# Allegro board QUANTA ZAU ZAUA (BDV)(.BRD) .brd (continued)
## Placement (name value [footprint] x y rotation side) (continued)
C20002  N16@4.7u/6.3V_4  [C0402_2]  105.67 107.97 0 top
C20003  N16@0.1u/16V_4  [C0402]  105.98 110.73 0 top
C20004  N16@1u/6.3V_4  [C0402]  104.2 109.84 0 top
C20005  EV@0.1u/16V_4  [C0402]  102.65 122.85 0 bottom
C20006  N16@0.1u/16V_4  [C0402]  119.53 124.33 270 top
C20016  N16@0.22u/10V_4  [C0402]  90.49 99.81 180 bottom
C20017  N16@1000p/50V_4  [C0402]  88.45 101.51 90 bottom
C20020  N16@1000p/50V_4  [C0402]  85.28 92.72 270 bottom
C20021  *N16@1000p/25V_2  [C0201]  84.96 94.8 270 top
C20022  47U/6.3V_6  [C0603]  108.01 50.28 90 top
C20023  *47U/6.3V_6  [C0603]  103.69 46.47 90 top
C20024  *180p/50V_4  [C0402]  150.94 22.9 90 top
C20025  180p/50V_4  [C0402]  56.45 103.52 90 bottom
C20026  180p/50V_4  [C0402]  60.13 102.22 270 bottom
CN1  50281-00201-001  [50281-00201-001-2P-L]  14.3 3.45 180 bottom
CN2  USB-097-1R09HG  [UB3-USB-097-1R09HG-9P]  7.4 54.44 90 bottom
CN3  USB-097-1R09HG  [UB3-USB-097-1R09HG-9P]  7.4 34.44 90 bottom
CN8  2RJ1622-001111F  [RJ45-2RJ1622-001111F-8P]  10.05 96.2 90 bottom
CN10  TPC@USB3.1  [UB31-C12321-1242D-L-24P]  1.46 15.9 90 bottom
CN13  KBL@50505-00401-V01  [50505-00401-V01-4P-L]  204.32 10.95 180 bottom
CN14  PBA@196241-08021-3  [196241-08021-3-8P-L]  58.7 18.15 180 bottom
CN15  ODD@132F18-100000-A2-R  [132F18-100000-A2-R-18P-L]  132.6 14.35 180 bottom
CN16  SSD@NASM0-S6701-TSH4  [NGFF-NASM0-S6701-TSH4-KM-SMT]  30.6 4.35 180 bottom
CN17  NASE0-S6701-TS40  [NGFF-NASE0-S6701-TS40-KE-SMT]  188.5 21.88 270 bottom
CN18  FOR15_17@196153-28021-35  [50584-0280N-V02-28P-L]  161.5 18.5 180 bottom
CN19  FOR14@196153-28021-35  [50584-0280N-V02-28P-L]  139.9 23.2 180 bottom
CN24  *51578-00401-V01  [FPC-51578-00401-V01-4P-L]  45.7 8.75 180 bottom
CN29  196538-40041-3  [196538-40041-3-40P-L]  53.6 110.3 0 bottom
CN33  51653-0080N-V02  [196047-08021-3-8P-L]  72.82 18.55 180 bottom
CN35  51619-04001-V04  [51619-04001-V04-40P-L]  216.25 38.15 270 bottom
CN36  51325-00401-001  [51325-00401-001-4P-L]  117.8 17.6 180 bottom
CN37  10444-19001  [HDMI-10591-19001-19P]  3.4 76.2 90 bottom
CN38  *50208-00401-V02  [50208-00401-V02-4P-L]  35.1 118.05 0 bottom
D3  1N4148WS  [D-SOD323-1_85X1_25-0_95H]  55.69 111.49 0 top
D4  EV@RB500V-40  [D-SOD323-1_85X1_25-0_95H]  90.1 99.3 270 top
D11  1N4148WS  [D-SOD323-1_85X1_25-0_95H]  192.26 33.01 270 bottom
D12  *RB500V-40  [D-SOD323-1_85X1_25-0_95H]  210.98 23.2 0 top
D13  RB500V-40  [D-SOD323-1_85X1_25-0_95H]  204.2 22.29 270 top
D14  BAT54AW-L  [SOT23-1_7-65-3P]  25.64 69.33 180 top
D16  TPC@EGA10402V05AH_0.2p  [R0402]  12.03 19.26 90 top
D17  TPC@EGA10402V05AH_0.2p  [R0402]  12.08 13.45 270 top
D18  TPC@EGA10402V05AH_0.2p  [R0402]  10.63 19.47 0 top
D19  TPC@EGA10402V05AH_0.2p  [R0402]  14.26 13.22 90 top
D20  GS@RB500V-40  [D-SOD323-1_85X1_25-0_95H]  51.14 15.3 0 top
D21  GS@RB500V-40  [D-SOD323-1_85X1_25-0_95H]  50.68 17.16 0 top
D22  *TPM@PESD5V0F1BL  [R0402]  130.08 21.35 0 top
D33  AZ5725-01F.R7G  [ESD-1X0_6-2P]  151.7 20.36 0 top
D50  *AZ5725-01F.R7G  [ESD-1X0_6-2P]  14.92 83.86 180 top
D51  *RB500V-40  [D-SOD323-1_85X1_25-0_95H]  167.45 30.49 0 top
D60  *RB500V-40  [D-SOD323-1_85X1_25-0_95H]  170.01 31 270 top
D61  RB500V-40  [D-SOD323-1_85X1_25-0_95H]  167.19 28.97 0 top
D62  *RB500V-40  [D-SOD323-1_85X1_25-0_95H]  167.19 27.44 0 top
D63  RB500V-40  [D-SOD323-1_85X1_25-0_95H]  177.23 23.48 270 top
D64  *RB500V-40  [D-SOD323-1_85X1_25-0_95H]  167.45 32.02 0 top
D65  TVM0G5R5M220R_22p  [R0402]  182.31 29.96 270 top
D2012  BAT54CW  [SOT23-1_7-65-3P]  50 26.55 180 top
D2016  *RB500V-40  [D-SOD323-1_85X1_25-0_95H]  167.19 25.92 0 top
D6541  TPC@P4SMAFJ20A  [D-3_8X2_5]  15.56 13.52 270 bottom
D6542  TPC@PDZ5.6B  [D-SOD323-1_7X1_25-PMEG4005AEA]  15.66 9.08 270 top
D6543  1N4148WS  [D-SOD323-1_85X1_25-0_95H]  193.79 33.26 270 bottom
D13081  *PESD5V0H1BSF  [D-0_6X0_3-0_32H-SMT]  13.9 79.87 0 top
D13082  *PESD5V0H1BSF  [D-0_6X0_3-0_32H-SMT]  13.9 78.85 0 top
D13083  *PESD5V0H1BSF  [D-0_6X0_3-0_32H-SMT]  13.78 77.96 270 bottom
D13084  *PESD5V0H1BSF  [D-0_6X0_3-0_32H-SMT]  13.78 76.57 90 bottom
D13085  *PESD5V0H1BSF  [D-0_6X0_3-0_32H-SMT]  13.78 75.93 270 top
D13086  *PESD5V0H1BSF  [D-0_6X0_3-0_32H-SMT]  13.78 74.54 90 top
D13087  *PESD5V0H1BSF  [D-0_6X0_3-0_32H-SMT]  13.78 82.03 270 bottom
D13088  *PESD5V0H1BSF  [D-0_6X0_3-0_32H-SMT]  13.78 80.63 90 bottom
D13089  *PESD5V0H1BSF  [D-0_6X0_3-0_32H-SMT]  13.78 74.79 270 bottom
D13090  *PESD5V0H1BSF  [D-0_6X0_3-0_32H-SMT]  13.78 73.39 90 bottom
EC7  *PBA@AZ5725-01F.R7G  [ESD-1X0_6-2P]  57.39 22.52 0 bottom
EC8  *PBA@AZ5725-01F.R7G  [ESD-1X0_6-2P]  59.22 22.52 0 bottom
EC9  SSD@10u/6.3V_4  [C0402_2]  25 4.76 0 top
EC10  SSD@10u/6.3V_4  [C0402_2]  26.53 6.87 90 top
EC11  SSD@0.1u/16V_2  [C0201]  27.01 8.88 0 top
EC12  *33p/50V_4  [C0402]  196.2 19.19 0 bottom
EC13  *220p/50V_4  [C0402]  167.42 16.98 270 top
EC6500  TPC@22u/6.3V_6  [C0603]  13.7 22.19 0 bottom
FAN3  50278-00401-001  [WTB-50278-00401-V01-4P-L]  171.72 29.5 90 bottom
HD1  HDD@51625-01201-001  [51625-01201-001-12P-L]  217.53 13.57 270 bottom
HE1  APX8132AI-TRG  [SOT23-2_38-95-3P]  34.9 122.75 90 top
HOLE1  *HG-O335X315D252X232P2  [HG-O335X315D252X232P2]  11.25 109.2 180 bottom
HOLE2  *HG-C354I158D118P2  [HG-C354I158D118P2]  17.48 68.15 0 top
HOLE3  *HG-ZAU-2  [HG-ZAU-2]  5.2 4.4 0 top
HOLE4  *HG-C354I274D220P2  [HG-C354I274D220P2]  86.2 15.5 180 bottom
HOLE5  EV@H-C256I186D102P2  [H-C256I186D102P2]  90.53 123.23 180 bottom
HOLE6  EV@H-C256I186D102P2  [H-C256I186D102P2]  119.53 84.23 180 bottom
HOLE7  *H-TIC157BC276D150P2  [H-TIC157BC276D150P2]  71.88 89.73 180 bottom
HOLE8  *H-TIC157BC276D150P2  [H-TIC157BC276D150P2]  71.88 27.73 180 bottom
HOLE9  *H-TIC157BC276D150P2  [H-TIC157BC276D150P2]  106.88 58.74 180 bottom
HOLE10  *H-S158D158N  [H-S158D158N]  110.17 72.38 0 top
HOLE11  *hg-zau-1  [HG-ZAU-1]  136.2 123.5 0 top
HOLE12  *H-C98D98N  [H-C98D98N]  142.5 123.5 180 bottom
HOLE13  *HG-C276D126P2  [HG-C276D126P2]  216.55 54 0 top
HOLE14  -  [H-DAVIDOFF-1]  216.8 21.88 180 bottom
HOLE15  *SPAD-DAVIDOFF-1  [SPAD-DAVIDOFF-1]  43.94 123.9 0 top
HOLE16  *SPAD-C354NP  [SPAD-C354NP]  41.2 10 0 top
HOLE17  *SPAD-C315NP  [SPAD-C315NP]  131.79 64.66 0 top
HOLE18  *SPAD-C354NP  [SPAD-C354NP]  140.49 22.1 0 top
HOLE19  *SPAD-RE209X315NP  [SPAD-RE209X315NP]  215.74 37.1 0 top
HOLE20  *SPAD-RE197X138NP  [SPAD-RE197X138NP]  3.35 108.2 90 bottom
HOLE21  *h-c79d79n  [H-C75D75N]  4.2 24 0 top
HOLE22  *2D-BARCODE-6X6-S  [2D-BARCODE-6X6-S]  18.02 104.15 0 bottom
J2000  *JUMP  [JOPEN25X30_S]  52.89 25.13 0 top
JDIM2000  D4AS0-26001-1P40  [DDR4-D4AS0-26001-1P40-STD-SMT]  54.35 62.83 270 bottom
L4  N17@HCB1005KF-330T30  [R0402]  113.22 84.82 90 bottom
L5  EV@HCB1608KF_300_2A  [R0603]  120.08 115.3 90 top
L7  N17@HCB1005KF-330T30  [R0402]  89.85 103.64 180 top
L8  N17@HCB1005KF-330T30  [R0402]  87.95 107.05 180 top
L11  BLM15AG121SN1D  [R0402]  202.07 19.19 180 top
L12  BLM15AG601SN1D  [R0402]  52.49 110.76 0 top
L13  BLM15AG601SN1D  [R0402]  51.14 111.14 270 top
L15  PBY160808T-600Y-N  [R0603]  210.37 29.45 0 top
L16  HCB2012KF-220T60  [R0805]  202.42 31.8 0 top
L23  HCB1005KF-330T30  [R0402]  75.3 18.05 270 top
L24  HCB1005KF-330T30  [R0402]  74.33 18.05 270 top
L28  HCB1608KF-121T30  [R0603]  210.63 33.64 0 bottom
L29  BLM15AG121SN1D  [R0402]  202.25 16.35 270 top
L30  BLM15AG121SN1D  [R0402]  183.93 31.86 270 top
L31  N16@HCB1005KF-330T30  [R0402]  89.92 104.63 180 top
L32  N16@HCB1005KF-330T30  [R0402]  88.33 105.52 270 top
NOREF  -  [unnamed]  127.85 122.72 0 top
NOREF#2  -  [#2]  62.93 70.47 0 top
NOREF#3  -  [#2]  82.61 -18.56 0 top
NOREF#4  -  [#2]  31.81 -59.2 0 top
NOREF#5  -  [unnamed]  23.56 116.19 0 top
NOREF#6  -  [unnamed]  208.51 43.28 0 top
NOREF#7  -  [#2]  26 23.86 180 bottom
NOREF#8  -  [unnamed]  129.6 121.78 180 bottom
NOREF#9  -  [unnamed]  208.6 43.42 180 bottom
NOREF#10  -  [unnamed]  25.29 115.81 180 bottom
PC1  1000p/50V_4  [C0402]  44 121.59 90 top
PC2  0.047u/50V_6  [C0603]  45.91 121.96 0 top
PC3  0.1u/25V_4  [C0402]  130.24 26.78 0 bottom
PC4  0.1u/25V_4  [C0402]  124.71 25.78 0 bottom
PC5  0.1u/50V_4  [C0402]  42 121.68 180 bottom
PC6  0.1u/25V_4  [C0402]  131.58 27.34 90 bottom
PC7  2200p/50V_4  [C0402]  134.04 40.84 270 top
PC8  0.01u/50V_4  [C0402]  133 27.29 90 top
PC9  2.2u/10V_4  [C0402]  132.15 29.22 90 top
PC10  *47p/50V_4  [C0402]  105.4 15.35 0 top
PC11  *47p/50V_4  [C0402]  103.95 15.1 270 top
PC12  0.1u/50V_4  [C0402]  135.23 40.39 270 top
PC13  2200p/50V_4  [C0402]  12 118.5 270 top
PC14  0.1u/50V_4  [C0402]  39.13 121.5 0 bottom
PC15  0.047u/50V_6  [C0603]  129.7 29.63 0 top
PC16  0.47u/25V_6  [C0603]  129.73 31.23 0 bottom
PC17  *0.01u/50V_4  [C0402]  123.62 28.59 90 top
PC18  *100p/50V_4  [C0402]  136.72 30.93 270 top
PC19  *680p/50V_6  [C0603]  128.28 28.21 180 top
PC20  100p/50V_4  [C0402]  136.72 32.65 270 top
PC25  0.1u/50V_4  [C0402]  132.9 33.9 90 bottom
PC35  0.1u/50V_4  [C0402]  133.13 32.53 90 top
PC36  0.1u/50V_4  [C0402]  134.09 32.53 270 top
PC37  100p/50V_4  [C0402]  138.14 33.67 0 bottom
PC51  2200p/50V_4  [C0402]  53.2 20.28 270 bottom
PC81  *0.1u/25V_4  [C0402]  113.42 34.37 270 bottom
PC82  *680p/50V_6  [C0603]  116.62 37.25 0 top
PC83  22u/6.3V_6  [C0603]  120.2 62.34 180 top
PC152  *2200p/50V_4  [C0402]  124.85 57.57 270 top
PC162  *330u/2V_7343H1.9  [CC7343]  62.6 88.1 90 bottom
PC164  22u/25V_8  [C0805]  111.32 34.33 180 bottom
PC165  2200p/50V_4  [C0402]  104.92 25.5 270 bottom
PC166  22u/25V_8  [C0805]  112.12 31.73 270 bottom
PC167  0.1u/50V_4  [C0402]  107.07 25.62 90 bottom
PC168  *100p/50V_4  [C0402]  105.88 25.5 270 bottom
PC170  10u/25V_8  [C0805]  114.89 34.07 270 bottom
PC172  2200p/50V_4  [C0402]  127.55 31.46 180 bottom
PC217  10u/25V_6  [C0603]  117.49 34.1 0 bottom
PC218  2200p/50V_4  [C0402]  127.78 43.8 90 bottom
PC219  *22U/6.3V_6  [C0603]  112.69 39.94 180 top
PC220  22u/6.3V_6  [C0603]  112.69 34.23 180 top
PC221  *0.01u/50V_4  [C0402]  125.63 35.57 270 bottom
PC222  22u/6.3V_6  [C0603]  116.14 35.19 270 top
PC224  22u/6.3V_6  [C0603]  112.69 37.1 180 top
PC225  *1000p/50V_4  [C0402]  122.29 36.77 0 bottom
PC227  22u/6.3V_6  [C0603]  114.72 34.25 270 top
PC228  *0.047u/6.3V_2  [C0201]  121.35 41.26 0 bottom
PC229  10u/6.3V_6  [C0603]  166.56 24.24 0 top
PC230  22u/6.3V_6  [C0603]  112.69 38.52 180 top
PC231  *22U/6.3V_6  [C0603]  112.69 35.65 180 top
PC232  0.047u/6.3V_2  [C0201]  119.04 41.39 90 bottom
PC233  0.1u/16V_4  [C0402]  117.36 35.55 270 top
PC234  10u/6.3V_6  [C0603]  117.28 41.74 0 bottom
PC235  0.1u/25V_4  [C0402]  114.9 40.17 180 top
PC236  *22U/6.3V_6  [C0603]  107.83 43.6 0 top
PC242  4.7u/6.3V_4  [C0402_2]  159.02 23.79 270 bottom
PC267  *150p/50V_4  [C0402]  69.4 122.01 270 top
PC268  1u/6.3V_2  [C0201]  61.1 125.46 0 top
PC276  *0.1u/16V_4  [C0402]  63.89 124.55 270 top
PC280  0.1u/16V_4  [C0402]  67.98 124.93 180 bottom
PC283  *0.1u/16V_4  [C0402]  65.26 124.17 180 top
PC285  *1u/6.3V_4  [C0402]  67.75 117.74 0 top
PC288  10u/25V_6  [C0603]  56.86 119.32 180 bottom
PC289  10u/25V_6  [C0603]  62.08 120.33 0 bottom
PC290  0.1u/25V_4  [C0402]  57.01 121.75 0 bottom
PC292  2200p/50V_4  [C0402]  57.01 120.79 0 bottom
PC293  *0.1u/16V_4  [C0402]  51.45 123.89 270 top
PC294  22u/6.3V_6  [C0603]  51.98 123.66 270 bottom
PC295  22u/6.3V_6  [C0603]  49.06 121.86 0 top
PC296  22u/6.3V_6  [C0603]  54.21 123.64 270 bottom
PC297  22u/6.3V_6  [C0603]  49.03 121.55 0 bottom
PC298  0.033u/10V_4  [C0402]  68.36 123.58 270 bottom
PC299  10u/6.3V_6  [C0603]  68.16 119.54 90 top
PC300  *2200p/50V_4  [C0402]  59.5 117.03 180 top
PC301  0.1u/25V_4  [C0402]  64.88 116.32 0 top
PC302  10u/6.3V_6  [C0603]  64.81 124.57 180 bottom
PC304  10u/6.3V_6  [C0603]  69.15 124.62 270 top
PC305  *22u/6.3V_8  [C0805]  56.37 123.86 270 bottom
PC306  *22u/6.3V_8  [C0805]  48.95 119.29 0 bottom
PC423  *0.1u/6.3V_2  [C0201]  138.01 59.68 90 bottom
PC551  *2200p/50V_6  [C0603]  36.76 31.74 180 top
PC561  0.1u/6.3V_2  [C0201]  37.02 27.7 270 top
PC562  22u/6.3V_6  [C0603]  35.34 27.42 0 top
PC563  22u/6.3V_6  [C0603]  33.84 29.58 270 top
PC571  10u/6.3V_4  [C0402_2]  45.02 30.19 270 top
PC572  0.01u/50V_4  [C0402]  43.93 30.19 270 top
PC574  *22p/50V_4  [C0402]  41.01 27.47 270 top
PC581  *0.1u/6.3V_2  [C0201]  39.41 27.55 270 top
PC756  0.1u/16V_4  [C0402]  139.95 30.17 180 bottom
PC6000  0.1u/25V_4  [C0402]  138.14 34.63 180 bottom
PC6001  0.1u/25V_4  [C0402]  148.1 35.14 90 bottom
PC6002  2200p/50V_4  [C0402]  142.49 30.75 270 bottom
PC6003  0.1u/25V_4  [C0402]  141.53 30.75 270 bottom
PC6004  22u/25V_8  [C0805]  141.12 32.6 0 bottom
PC6005  *10u/25V_6  [C0603]  141.1 34.57 0 bottom
PC6006  *680p/50V_6  [C0603]  142.3 28.71 0 bottom
PC6007  0.1u/16V_4  [C0402]  144.52 31.41 270 top
PC6008  22u/6.3V_6  [C0603]  156.48 35.77 270 bottom
PC6009  22u/6.3V_6  [C0603]  150.13 35.19 0 top
PC6010  22u/6.3V_6  [C0603]  156.96 35.47 270 top
PC6011  *22U/6.3V_6  [C0603]  155.48 35.34 270 top
PC6012  *22U/6.3V_6  [C0603]  159.07 35.65 180 top
PC6013  0.1u/16V_4  [C0402]  159.47 35.5 180 bottom
PC6014  22u/6.3V_6  [C0603]  157.89 35.77 270 bottom
PC6015  1u/25V_4  [C0402]  157.41 27.6 180 top
PC6016  1u/25V_4  [C0402]  152.61 27.93 90 top
PC6017  0.1u/16V_4  [C0402]  144.37 33.12 180 top
PC6018  10u/6.3V_6  [C0603]  158.05 23.48 90 top
PC6019  0.1u/16V_4  [C0402]  156.86 23.58 90 top
PC6020  0.1u/16V_4  [C0402]  153.96 23.63 90 top
PC6021  10u/6.3V_6  [C0603]  152.74 23.56 90 top
PC6022  1u/10V_4  [C0402]  143.95 34.38 0 bottom
PC6023  4.7u/6.3V_4  [C0402_2]  144.04 35.73 270 bottom
PC6024  10P/50V_4  [C0402]  144.31 35.34 0 top
PC6025  0.1u/16V_4  [C0402]  154.14 27.72 0 bottom
PC6026  *0.1u/16V_4  [C0402]  156.55 29.07 90 bottom
PC6027  *0.1u/16V_4  [C0402]  152.41 27.72 180 bottom
PC6028  1000p/50V_4  [C0402]  155.89 23.58 90 top
PC6029  1000p/50V_4  [C0402]  154.93 23.58 90 top
PC6030  0.1u/25V_4  [C0402]  50.55 18.63 270 bottom
PC6031  0.1u/25V_4  [C0402]  48.79 18.79 90 bottom
PC6032  22u/25V_8  [C0805]  51.27 15.64 90 bottom
PC6033  *10u/25V_6  [C0603]  47.31 18.84 270 bottom
PC6034  2200p/50V_4  [C0402]  51.51 18.63 90 bottom
PC6035  0.1u/25V_4  [C0402]  40.56 16.37 0 top
PC6036  1u/25V_4  [C0402]  24.01 23.02 180 top
PC6037  1u/25V_4  [C0402]  23.05 30.01 270 top
PC6038  *680p/50V_6  [C0603]  43.62 18.4 270 top
PC6039  0.1u/16V_4  [C0402]  49.31 14.51 270 bottom
PC6040  10u/6.3V_6  [C0603]  21.75 23.15 270 top
PC6041  0.1u/16V_4  [C0402]  21.3 24.98 180 top
PC6042  0.1u/16V_4  [C0402]  21.7 29.63 180 top
PC6043  10u/6.3V_6  [C0603]  18.73 29.58 0 top
PC6044  22u/6.3V_6  [C0603]  31.74 19.53 270 bottom
PC6045  22u/6.3V_6  [C0603]  37.03 15.92 180 top
PC6046  22u/6.3V_6  [C0603]  34.6 13.17 0 bottom
PC6047  22u/6.3V_6  [C0603]  37.03 18.19 180 top
PC6048  *22U/6.3V_6  [C0603]  36.76 19.93 180 top
PC6049  *22U/6.3V_6  [C0603]  34.76 15.02 90 top
PC6050  0.1u/16V_4  [C0402]  32.73 14.08 90 bottom
PC6051  0.1u/16V_4  [C0402]  24.95 27.34 180 top
PC6052  *0.1u/16V_4  [C0402]  24.95 26.38 180 top
PC6053  *0.1u/16V_4  [C0402]  24.95 28.31 180 top
PC6054  4.7u/10V_4  [C0402]  42.42 14.17 90 bottom
PC6055  0.1u/16V_4  [C0402]  44.59 15.23 270 bottom
PC6056  1000p/50V_4  [C0402]  18.78 26.88 0 top
PC6057  1000p/50V_4  [C0402]  18.78 27.9 0 top
PC6058  1u/10V_4  [C0402]  43.62 15.23 90 bottom
PC6059  10P/50V_4  [C0402]  45.93 13.77 180 bottom
PC6228  0.1u/16V_4  [C0402]  77.89 25.67 90 bottom
PC6229  0.47u/6.3V_4  [C0402]  162.49 26.28 270 top
PC6230  10u/6.3V_6  [C0603]  171.89 22.47 180 bottom
PC6231  0.1u/16V_4  [C0402]  170.06 22.59 270 bottom
PC7000  0.22u/25V_4  [C0402]  135.32 50.02 90 top
PC7001  1000p/50V_4  [C0402]  140.27 58.15 90 top
PC7003  *0.1u/6.3V_2  [C0201]  141.79 56.76 0 top
PC7004  0.47u/6.3V_2  [C0201]  140.65 53.83 180 top
PC7005  *0.1u/6.3V_2  [C0201]  143.22 60.64 0 bottom
PC7006  *0.1u/6.3V_2  [C0201]  141.79 53.83 180 top
PC7007  *100p/50V_4  [C0402]  145.58 50.38 180 top
PC7008  *100p/50V_4  [C0402]  143.6 51.29 0 top
PC7009  *100p/50V_4  [C0402]  145.58 49.41 180 top
PC7010  330p/16V_2  [C0201]  143.95 46.72 90 bottom
PC7011  82p/50V_4  [C0402]  142.45 48.17 180 bottom
PC7012  *68p/50V_4  [C0402]  143.01 45.1 90 bottom
PC7013  *100p/50V_4  [C0402]  138.36 57.52 90 top
PC7014  *100p/50V_4  [C0402]  133.41 60.03 0 bottom
PC7015  *100p/50V_4  [C0402]  135.7 56.88 180 top
PC7016  270p/50V_4  [C0402]  133.4 56.11 0 bottom
PC7017  82p/50V_4  [C0402]  133.4 58.06 180 bottom
PC7018  *68p/50V_4  [C0402]  133.4 54.17 0 bottom
PC7019  *100p/50V_4  [C0402]  144.12 51.31 0 bottom
PC7020  560p/50V_4  [C0402]  145.89 51.26 180 bottom
PC7021  68p/50V_4  [C0402]  144.77 54.88 270 bottom
PC7022  *100p/50V_4  [C0402]  143.5 53.28 180 top
PC7023  *68p/50V_4  [C0402]  145.25 53.1 180 top
PC7024  *100p/50V_4  [C0402]  144.2 53.51 180 bottom
PC7025  0.1u/6.3V_2  [C0201]  137.86 48.37 270 bottom
PC7026  4.7u/6.3V_4  [C0402]  135.7 51.8 180 top
PC7027  0.1u/6.3V_2  [C0201]  139.76 45.06 90 bottom
PC7029  0.1u/6.3V_2  [C0201]  143.65 56.53 270 bottom
PC7030  0.1u/6.3V_2  [C0201]  136.21 59.68 270 bottom
PC7031  22u/25V_8  [C0805]  131 69.07 90 bottom
PC7032  *10u/25V_6  [C0603]  128.54 73.67 270 bottom
PC7033  10u/25V_6  [C0603]  130.52 73.67 270 bottom
PC7034  0.1u/25V_4  [C0402]  131.08 70.17 90 top
PC7035  2200p/50V_4  [C0402]  132.04 70.17 270 top
PC7036  *15u/25V_3528H1.9  [C3528]  129.52 33.64 180 bottom
PC7037  *10u/25V_8  [C0805]  123.35 69.3 90 bottom
PC7038  0.1u/25V_4  [C0402]  133.03 70.17 90 top
PC7039  *0.1u/16V_4  [C0402]  116.27 60.18 180 top
PC7040  22u/6.3V_6  [C0603]  109.79 67.68 270 bottom
PC7041  22u/6.3V_6  [C0603]  111.82 67.68 270 bottom
PC7042  *22u/6.3V_8  [C0805]  115 64.63 180 bottom
PC7043  *22u/6.3V_8  [C0805]  113.85 67.68 270 bottom
PC7044  *330u/2V_7343H1.9  [CC7343]  119.16 51.17 270 bottom
PC7045  330u/2V_7343H1.9  [CC7343]  119.19 61.76 90 bottom
PC7046  *2200p/50V_4  [C0402]  130.85 65.34 180 bottom
PC7047  0.47u/6.3V_4  [C0402]  138.75 48.5 90 bottom
PC7049  U42P@22u/25V_8  [C0805]  123.12 47.81 270 bottom
PC7050  *U42P@10u/25V_6  [C0603]  122.49 45.2 0 bottom
PC7051  U42P@10u/25V_6  [C0603]  130.87 48.58 270 bottom
PC7052  *U42P@10u/25V_6  [C0603]  130.87 44.36 90 bottom
PC7053  U42P@0.1u/25V_4  [C0402]  126.81 43.8 90 bottom
PC7054  U42P@2200p/50V_4  [C0402]  125.79 43.8 270 bottom
PC7055  U42P@0.1u/25V_4  [C0402]  124.78 43.8 90 bottom
PC7056  U42P@0.22u/25V_4  [C0402]  133.31 44.82 0 bottom
PC7057  U42P@0.1u/16V_4  [C0402]  122.92 49.97 0 bottom
PC7058  U42P@22u/6.3V_6  [C0603]  109.08 47.99 90 bottom
PC7059  U42P@22u/6.3V_6  [C0603]  100.98 51.83 90 bottom
PC7060  U42P@22u/6.3V_6  [C0603]  111.06 47.99 90 bottom
PC7061  U42P@22u/6.3V_6  [C0603]  107.07 49.52 90 bottom
PC7062  U42P@330u/2V_7343H1.9  [CC7343]  114.41 51.17 270 bottom
PC7063  U42P@1u/6.3V_4  [C0402]  134.86 50.46 180 bottom
PC7064  *U42P@2200p/50V_4  [C0402]  131.38 51.7 270 bottom
PC7065  U42P@0.47u/6.3V_4  [C0402]  139.76 48.5 90 bottom
PC7066  22u/25V_8  [C0805]  139.3 37.17 270 bottom
PC7067  *10u/25V_6  [C0603]  141.41 37.2 270 bottom
PC7068  0.1u/25V_4  [C0402]  141.57 38.06 180 top
PC7069  2200p/50V_4  [C0402]  141.9 36.14 0 top
PC7070  0.1u/25V_4  [C0402]  141.9 37.1 180 top
PC7072  22u/6.3V_6  [C0603]  114.97 44.64 270 bottom
PC7073  22u/6.3V_6  [C0603]  112.94 44.69 270 bottom
PC7074  *22u/6.3V_8  [C0805]  124.47 41.9 180 bottom
PC7075  *22u/6.3V_8  [C0805]  119.8 44.74 270 bottom
PC7076  *22u/6.3V_8  [C0805]  124.14 37.07 90 bottom
PC7077  *22u/6.3V_8  [C0805]  116.95 44.74 270 bottom
PC7078  *2200p/50V_4  [C0402]  137.83 40.69 90 top
PC7079  0.47u/6.3V_4  [C0402]  143.95 56.73 180 top
PC7080  10u/25V_6  [C0603]  124 78.85 315 bottom
PC7081  *10u/25V_6  [C0603]  116.64 72.79 315 bottom
PC7082  *10u/25V_6  [C0603]  121.32 70.27 90 bottom
PC7083  22u/25V_8  [C0805]  119.14 73.16 315 bottom
PC7084  0.1u/25V_4  [C0402]  124.04 78.19 315 top
PC7085  2200p/50V_4  [C0402]  124.75 78.95 135 top
PC7086  0.1u/25V_4  [C0402]  123.28 79.44 225 top
PC7087  *0.1u/16V_4  [C0402]  93.15 79.92 315 top
PC7088  22u/6.3V_6  [C0603]  77.66 83.37 180 bottom
PC7089  22u/6.3V_6  [C0603]  72.32 84.77 270 bottom
PC7090  *22u/6.3V_8  [C0805]  77.66 81.19 180 bottom
PC7091  *22u/6.3V_8  [C0805]  83.79 84.04 90 bottom
PC7092  *22u/6.3V_8  [C0805]  81.62 85.96 90 bottom
PC7093  *22u/6.3V_8  [C0805]  70.34 84.77 270 bottom
PC7094  330u/2V_7343H1.9  [CC7343]  104.71 78.09 270 bottom
PC7095  *330u/2V_7343H1.9  [CC7343]  107.69 85.2 0 bottom
PC7096  *2200p/50V_4  [C0402]  120.16 78.28 45 top
PC7097  0.47u/6.3V_4  [C0402]  133.49 58.28 0 top
PC7099  0.1u/25V_4  [C0402]  143.32 57.69 180 top
PC7100  *1000p/25V_4  [C0402]  133.49 57.26 0 top
PC7101  0.22u/25V_4  [C0402]  127.9 76.43 0 top
PC7102  1u/6.3V_4  [C0402]  129.7 78.55 90 bottom
PC7103  0.22u/25V_4  [C0402]  140.63 40.2 0 top
PC7104  1u/6.3V_4  [C0402]  142.8 41.1 0 bottom
PC7105  0.22u/25V_4  [C0402]  118.78 70.29 180 top
PC7106  1u/6.3V_4  [C0402]  116.98 68.11 270 bottom
PC9000  EV@2.2u/10V_4  [C0402]  79.11 110.84 180 top
PC9001  *EV@10u/25V_6  [C0603]  73.12 121.79 180 top
PC9002  EV@10u/25V_6  [C0603]  72.62 124.73 180 top
PC9003  EV@0.1u/25V_4  [C0402]  62.19 118.81 0 bottom
PC9004  EV@1u/25V_6  [C0603]  69.02 112.1 0 top
PC9005  EV@10u/25V_6  [C0603]  72.67 123.28 180 top
PC9006  EV@2200p/50V_4  [C0402]  62.15 121.81 0 bottom
PC9007  *EV@15u/25V_3528H1.9  [C3528]  71.57 123.56 180 bottom
PC9008  EV@0.22u/25V_4  [C0402]  76.69 114.41 0 top
PC9009  EV@22u/6.3V_6  [C0603]  108.69 122.23 0 bottom
PC9010  EV@330u/2V_7343H1.9  [CC7343]  80.63 121.47 180 top
PC9011  EV@330u/2V_7343H1.9  [CC7343]  115 123.61 0 bottom
PC9012  *EV@2200p/50V_4  [C0402]  74.99 118.17 0 top
PC9013  N17@0.22u/10V_4  [C0402]  72.5 115.76 0 top
PC9014  *EV@0.22u/10V_4  [C0402]  71.94 106.67 270 top
PC9015  *EV@10u/25V_6  [C0603]  81.47 101.46 90 bottom
PC9016  *EV@10u/25V_6  [C0603]  79.46 101.46 90 bottom
PC9017  EV@22u/25V_8  [C0805]  83.45 101.46 90 bottom
PC9018  EV@0.1u/25V_4  [C0402]  78.5 106.01 270 bottom
PC9019  EV@2200p/50V_4  [C0402]  77.51 106.01 270 bottom
PC9020  EV@0.22u/25V_4  [C0402]  77.81 108.34 45 top
PC9021  EV@330u/2V_7343H1.9  [CC7343]  110.25 123.43 180 top
PC9022  EV@22u/6.3V_6  [C0603]  108.62 124.95 0 bottom
PC9023  EV@0.1u/16V_4  [C0402]  69.56 113.32 0 top
PC9024  *EV@2200p/50V_4  [C0402]  83.07 106.59 0 top
PC9025  SP@4700p/25V_4  [C0402]  74.1 112.91 90 bottom
PC9026  EV@1500p/50V_4  [C0402]  70.67 114.29 180 top
PC9027  EV@56p/50V_4  [C0402]  69.48 108.75 0 bottom
PC9028  *EV@100p/50V_4  [C0402]  69.89 110.3 270 bottom
PC9029  EV@56p/50V_4  [C0402]  69.51 111.64 0 bottom
PC9030  *EV@56p/50V_4  [C0402]  73.7 108.62 270 bottom
PC9053  EV@1u/25V_4  [C0402]  20.9 90.28 90 top
PC9054  EV@1u/25V_4  [C0402]  25.11 90.28 90 top
PC9055  EV@10u/6.3V_4  [C0402]  20.76 98.41 0 top
PC9056  EV@0.1u/16V_4  [C0402]  20.76 97.14 0 top
PC9057  EV@0.1u/16V_4  [C0402]  25.46 95.24 180 top
PC9058  EV@10u/6.3V_4  [C0402]  25.46 96.51 180 top
PC9059  EV@0.1u/16V_4  [C0402]  22.9 90.28 90 top
PC9060  *EV@0.1u/16V_4  [C0402]  23.91 90.28 90 top
PC9062  EV@1000p/50V_4  [C0402]  22.41 96.63 270 top
PC9063  EV@1000p/50V_4  [C0402]  23.43 96.63 270 top
PC9064  *EV@820p/50V_4  [C0402]  21.88 90.28 90 top
PC9065  EV@0.1u/16V_4  [C0402]  63.51 95.77 0 bottom
PC9066  EV@10u/6.3V_6  [C0603]  63.38 94.5 0 bottom
PC9067  EV@10u/6.3V_6  [C0603]  70.04 95.74 180 bottom
PC9068  EV@10u/6.3V_6  [C0603]  70.04 97.27 180 bottom
PC9069  EV@0.1u/16V_4  [C0402]  70.17 94.47 180 bottom
PC9071  EV@0.01u/50V_4  [C0402]  76.77 93.08 90 bottom
PC9072  EV@0.1u/16V_4  [C0402]  77 99.96 180 bottom
PC9073  EV@0.22u/10V_4  [C0402]  77.79 93.84 90 bottom
PC9074  *EV@0.01u/50V_4  [C0402]  139.13 62.09 180 bottom
PC9075  EV@10u/6.3V_6  [C0603]  141.59 72.09 180 bottom
PC9076  *EV@0.1u/25V_4  [C0402]  137.02 62.83 0 top
PC9077  EV@2200p/50V_4  [C0402]  135.75 61.25 0 bottom
PC9078  EV@10u/25V_8  [C0805]  136.46 62.75 0 bottom
PC9079  EV@0.1u/25V_4  [C0402]  137.96 70.34 180 bottom
PC9080  EV@22u/6.3V_6  [C0603]  142.1 74.38 90 bottom
PC9081  EV@22u/6.3V_6  [C0603]  139.23 74.36 90 bottom
PC9082  EV@22u/6.3V_6  [C0603]  142.25 74.38 90 top
PC9083  EV@22u/6.3V_6  [C0603]  140.8 74.38 90 top
PC9084  EV@22u/6.3V_6  [C0603]  139.38 74.36 90 top
PC9085  *EV@22U/6.3V_6  [C0603]  137.96 74.36 90 top
PC9086  *EV@22U/6.3V_6  [C0603]  140.65 74.38 90 bottom
PC9087  EV@0.1u/16V_4  [C0402]  136.74 74.66 90 top
PC9088  *EV@680p/50V_6  [C0603]  136.64 67.91 270 top
PC9089  *EV@1000p/50V_4  [C0402]  141.46 64.78 180 bottom
PC9090  EV@1u/6.3V_2  [C0201]  141.69 67.83 0 bottom
PC9091  EV@0.01u/50V_4  [C0402]  140.53 69.47 180 bottom
PC9097  *22p/50V_4  [C0402]  161.1 26.91 180 top
PC9098  *22U/6.3V_6  [C0603]  35.37 29.58 270 top
PD2  P4SMAFJ20A  [D-3_8X2_5]  16.5 115.18 180 top
PD3  PDZ5.6B  [D-SOD323-1_7X1_25-PMEG4005AEA]  107.91 16.85 90 top
PD4  PDZ5.6B  [D-SOD323-1_7X1_25-PMEG4005AEA]  109.41 16.62 90 top
PD9001  EV@1SS355  [D-SOD323-1_85X1_25-0_95H]  75.12 96.51 90 bottom
PD9002  BAT54CW  [SOT23-1_7-65-3P]  132.4 35.29 0 top
PJ1  50458-00801-V02  [WTB-50458-00801-V02-8P-L]  102.45 16.42 180 bottom
PJ2  SP@30706-00042-001  [DCJK-30706-00042-001-3P-SMT]  1.85 116.6 90 bottom
PJ3005  0.001_1%_3720  [RC3720-SMT]  107.71 35.83 0 top
PJ3008  0.001_1%_3720  [RC3720-SMT]  165.8 21.58 0 top
PJ6001  0.001_1%_3720  [RC3720-SMT]  154.85 32.12 180 top
PJ6003  0.001_1%_3720  [RC3720-SMT]  33.59 18.53 90 top
PJ7001  *short3720  [SHORT3720]  51.27 116.32 180 bottom
PJ9002  EV@0.001_1%_3720  [RC3720-SMT]  140.65 78.6 180 bottom
PJ9003  *EV@short_8  [S0805]  70.17 99.05 180 bottom
PJ9005  0.001_1%_3720  [RC3720-SMT]  30.95 29.96 180 top
PL5  6.8uH/4.5A_7x7x3  [L6_6X6_6-2_8H]  118.93 28.9 180 bottom
PL12  1uH/11A_7x7x3  [L6_6X6_6-2_8H]  109.92 38.72 180 bottom
PL14  2.2uH/1.67A_2.5x2.0x1.2  [L2_5X2-1_2H]  166.56 22.97 0 bottom
PL30  1uH/11A_7x7x3  [L6_6X6_6-2_8H]  56.6 121.86 180 top
PL551  1uH/3.35A_2.5x2.0x1.2  [L2_5X2-1_2H]  37.78 29.58 180 top
PL6000  1uH/11A_7x7x3  [L6_6X6_6-2_8H]  152.21 32.12 0 bottom
PL6001  1uH/11A_7x7x3  [L6_6X6_6-2_8H]  37.07 17.46 180 bottom
PL7000  0.15uH/37A_7x7x3  [CHOKE-PCMC063T-3R3MN-SMT]  126.1 61.97 180 bottom
PL7001  U42P@0.15uH/37A_7x7x3  [CHOKE-PCMC063T-3R3MN-SMT]  126.1 54.99 180 bottom
PL7002  0.47uH/17.5A_7x7x3  [CHOKE-PCMC063T-3R3MN-SMT]  129.73 38.85 180 bottom
PL7003  0.15uH/37A_7x7x3  [CHOKE-PCMC063T-3R3MN-SMT]  112 79.03 180 bottom
PL9000  EV@0.22uH/23A_7x7x3  [CHOKE-PCMC063T-3R3MN-SMT]  84.62 113.43 0 bottom
PL9001  EV@0.22uH/23A_7x7x3  [CHOKE-PCMC063T-3R3MN-SMT]  81.55 120.42 0 bottom
PL9002  EV@0.68uH/15.5A_7x7x3  [CHOKE-PCMC063T-3R3MN-SMT]  135.04 74.43 90 bottom
PQ1  AON6414AL  [POWER-5_2X5_55-1_27-5P]  40.12 119.49 0 top
PQ2  AON6414AL  [POWER-5_2X5_55-1_27-5P]  122.75 33.11 270 top
PQ6  2N7002K  [SOT23-2-95-3P]  50.94 21.35 90 bottom
PQ7  DDTC144EUA-7-F  [SOT23-1_7-65-3P]  126.81 51.17 180 top
PQ9  AO3404  [SOT23-2_38-95-3P]  30.01 33.56 180 top
PQ10  2N7002K  [SOT23-2-95-3P]  125.18 54.9 0 top
PQ11  AO3404  [SOT23-2_38-95-3P]  120.64 64.91 0 top
PQ12  *2N7002K  [SOT23-2-95-3P]  31.25 10.17 0 top
PQ14  2N7002K  [SOT23-2-95-3P]  108.4 32.13 270 bottom
PQ16  DDTC144EUA-7-F  [SOT23-1_7-65-3P]  25.59 31.69 0 top
PQ17  2N7002KW  [SOT23-1_7-65-3P]  140.78 33.39 90 top
PQ19  *2N7002K  [SOT23-2-95-3P]  107.26 28.75 90 bottom
PQ25  2N7002K  [SOT23-2-95-3P]  123.46 51.47 270 top
PQ29  AON7410  [DFN-8L-3X3-65-5P-0_9H]  125.49 28.9 0 bottom
PQ30  AON7410  [DFN-8L-3X3-65-5P-0_9H]  124.99 32.76 270 bottom
PQ35  AON7408  [DFN-8L-3X3-65-5P-0_9H]  107.2 39.66 90 top
PQ6000  2N7002K  [SOT23-2-95-3P]  142.49 29.32 270 top
PQ6001  2N7002K  [SOT23-2-95-3P]  46.34 14.58 180 top
PQ7000  AOE6932  [POWER-5X6-1_27-10P]  127.16 68.79 0 bottom
PQ7001  U42P@AOE6932  [POWER-5X6-1_27-10P]  127.14 48.16 180 bottom
PQ7002  AON7410  [DFN-8L-3X3-65-5P-0_9H]  136.33 37.07 90 bottom
PQ7003  AON7752  [DFN-8L-3X3-65-5P-0_9H]  136.36 41.01 0 bottom
PQ7004  AOE6936  [POWER-5X6-1_27-10P]  121.52 76.11 225 bottom
PQ9000  EV@AOE6936  [POWER-5X6-1_27-10P]  73.77 119.11 90 bottom
PQ9001  EV@AOE6936  [POWER-5X6-1_27-10P]  81.77 106.41 180 bottom
PQ9008  EV@AON7408  [DFN-8L-3X3-65-5P-0_9H]  66.76 94.47 0 bottom
PQ9009  EV@2N7002K  [SOT23-2-95-3P]  70.42 103.75 90 bottom
PQ9010  EV@DMG1012T-7  [SOT23-1_38-5-3P]  77.01 102.53 270 bottom
PQ9011  EV@2N7002K  [SOT23-2-95-3P]  74.36 100.06 90 bottom
PQ9050  2N7002K  [SOT23-2-95-3P]  10.88 19.44 0 bottom
PQ9054  AON6414AL  [POWER-5_2X5_55-1_27-5P]  46.93 117.35 180 top
PQ9083  EV@DDTC144EUA-7-F  [SOT23-1_7-65-3P]  127.06 122.29 270 bottom
PQ9084  EV@2N7002KW  [SOT23-1_7-65-3P]  122.03 122.8 180 top
PQ9085  EV@2N7002K  [SOT23-2-95-3P]  135.8 77.91 180 top
PQ9086  EV@DMG1012T-7  [SOT23-1_38-5-3P]  131.91 77.13 270 top
PR1  *short_2  [S0201]  54.54 113.47 0 top
PR2  *short_2  [S0201]  54.54 114.21 0 top
PR3  0.01_1%_0612  [RC3216]  51.9 116.32 90 top
PR4  *short_6  [S0603]  124.83 28.4 90 top
PR5  *short_2  [S0201]  132.42 27.11 270 bottom
PR6  *short_2  [S0201]  133.28 26.68 180 bottom
PR7  10_1%_6  [R0603]  122.41 27.73 90 top
PR8  *short_2  [S0201]  138.03 28.33 180 top
PR9  10K_5%_4  [R0402]  137.07 26.83 180 bottom
PR10  *0_5%_2  [R0201]  109.41 22.96 0 bottom
PR11  *short_6  [S0603]  129.73 29.63 0 bottom
PR12  100_5%_2  [R0201]  102.93 15.1 270 top
PR13  100_5%_2  [R0201]  105.4 16.34 0 top
PR14  100_5%_2  [R0201]  100.8 21.7 180 top
PR15  *10K_5%_4  [R0402]  138.19 28.15 180 bottom
PR16  20_5%_12  [R1206]  129.32 32.71 0 top
PR17  *short_2  [S0201]  138.47 29.32 180 bottom
PR18  1M_5%_4  [R0402]  98.97 21.7 0 top
PR19  *short_2  [S0201]  138.47 30.03 180 bottom
PR22  *100K_1%_2  [R0201]  138.01 30.76 0 bottom
PR23  SP@41.2K_1%_4  [R0402]  137.68 31.23 90 top
PR25  *short_2  [S0201]  138.04 31.47 180 bottom
PR26  *short_2  [S0201]  138.06 32.29 0 bottom
PR28  4.02K_1%_4  [R0402]  133.87 33.87 90 bottom
PR29  4.02K_1%_4  [R0402]  134.83 33.87 90 bottom
PR30  *short_2  [S0201]  134.93 33.58 270 top
PR31  866K_1%_4  [R0402]  135.8 33.87 90 bottom
PR32  *short_2  [S0201]  136.71 32.63 180 bottom
PR33  *4.7_5%_6  [R0603]  126.26 29.22 90 top
PR39  100K_1%_4  [R0402]  132.15 30.94 270 top
PR40  100K_1%_4  [R0402]  135.76 32.52 90 top
PR59  1M_5%_6  [R0603]  52.97 18.1 270 bottom
PR79  1M_5%_6  [R0603]  128.18 53.17 0 top
PR80  1M_5%_6  [R0603]  127.67 55.21 270 top
PR98  *0_5%_2  [R0201]  121.35 40.5 0 bottom
PR99  *4.7_5%_6  [R0603]  116.62 38.67 180 top
PR104  10_5%_6  [R0603]  119.77 39.81 0 top
PR105  22_5%_8  [R0805]  120.69 50.35 270 top
PR106  *22_5%_8  [R0805]  27.95 10.3 180 top
PR111  22_5%_8  [R0805]  106.2 34.32 180 bottom
PR116  1M_5%_6  [R0603]  106.39 22.97 270 top
PR118  1M_5%_6  [R0603]  7.78 23.05 270 top
PR120  *100K_1%_6  [R0603]  27.16 28.94 90 top
PR126  *220_5%_8  [R0805]  102.83 26.25 180 bottom
PR191  1M_5%_6  [R0603]  126.66 57.39 0 top
PR204  316K_1%_4  [R0402]  134.35 27.36 180 top
PR205  *0_5%_2  [R0201]  136.73 28.75 0 top
PR206  100K_1%_4  [R0402]  131.74 27.44 270 top
PR207  100K_5%_4  [R0402]  137.1 29.58 0 top
PR208  *short_2  [S0201]  121.76 25 180 bottom
PR209  0.01_1%_0612  [RC3216]  112.75 28.24 90 bottom
PR210  *short_2  [S0201]  122.98 25.82 180 bottom
PR211  137K_1%_4  [R0402]  136.76 33.87 90 bottom
PR230  1M_5%_6  [R0603]  138.24 34.91 90 top
PR235  1M_5%_6  [R0603]  136.08 35.67 180 top
PR253  10K_1%_4  [R0402]  67.47 121.73 270 top
PR254  100_1%_4  [R0402]  66.94 123.58 270 bottom
PR256  2.2_5%_6  [R0603]  62.67 124.62 90 top
PR261  499K_1%_2  [R0201]  61.1 124.5 0 top
PR262  *short_6  [S0603]  66.53 115.76 90 top
PR263  6.04K_1%_2  [R0201]  68.44 121.73 90 top
PR265  *short_2  [S0201]  66.33 125.02 0 top
PR266  *0_5%_2  [R0201]  64.88 125.02 0 top
PR267  *short_2  [S0201]  62.34 123.99 90 bottom
PR268  73.2K_1%_4  [R0402]  120.79 35.42 90 bottom
PR269  SP@4.99K_1%_4  [R0402]  122.19 35.8 180 bottom
PR270  20K_1%_4  [R0402]  122.01 37.88 180 bottom
PR272  *short_2  [S0201]  121.35 39.74 0 bottom
PR273  *short_4  [S0402]  121.98 38.85 180 bottom
PR274  *short_2  [S0201]  121.35 42.02 0 bottom
PR275  100K_1%_2  [R0201]  119.75 41.39 90 bottom
PR276  *short_2  [S0201]  120.46 41.39 90 bottom
PR277  2.2_5%_6  [R0603]  117.08 40.09 180 top
PR283  15K_1%_4  [R0402]  161.1 25.89 180 top
PR284  *short_2  [S0201]  164.4 28.69 0 top
PR551  *2.2_5%_6  [R0603]  39.41 31.74 0 top
PR566  *short_2  [S0201]  38.7 27.55 270 top
PR567  10K_1%_4  [R0402]  43.34 27.85 0 top
PR568  20K_1%_4  [R0402]  42 27.47 270 top
PR569  *short_2  [S0201]  37.83 27.7 90 top
PR2060  *short_2  [S0201]  104.83 41.22 180 top
PR3020  150_5%_2  [R0201]  76.92 25.67 90 bottom
PR3021  29.4K_1%_4  [R0402]  83.3 25.69 90 bottom
PR3022  *short_2  [S0201]  77.91 24.12 180 bottom
PR6000  10_1%_6  [R0603]  146.88 35.42 90 bottom
PR6001  *4.7_5%_6  [R0603]  144.94 28.92 0 bottom
PR6002  *short_2  [S0201]  142.89 32.87 90 top
PR6003  10K_1%_4  [R0402]  143.85 37.48 270 bottom
PR6004  *short_2  [S0201]  143.52 38.84 90 bottom
PR6005  *short_2  [S0201]  143.09 33.29 90 bottom
PR6006  10K_1%_4  [R0402]  143.56 31.41 270 top
PR6007  100K_1%_4  [R0402]  142.88 37.47 270 bottom
PR6008  *short_2  [S0201]  155.23 36.21 90 bottom
PR6009  10K_1%_4  [R0402]  144.21 34.38 180 top
PR6010  *1K_1%_4  [R0402]  145.71 33.06 270 top
PR6011  1K_1%_4  [R0402]  145.96 34.78 90 top
PR6012  *100K_1%_4  [R0402]  140.23 30.82 270 top
PR6013  *short_4  [S0402]  155.87 27.72 0 bottom
PR6014  *10K_1%_4  [R0402]  146.22 31.33 270 top
PR6015  *short_2  [S0201]  157.67 29.55 0 bottom
PR6016  *short_2  [S0201]  151.04 27.72 0 bottom
PR6017  *short_6  [S0603]  145.45 36.28 270 bottom
PR6018  10_1%_6  [R0603]  40.19 17.59 180 top
PR6019  *4.7_5%_6  [R0603]  40.97 19.26 180 top
PR6020  *short_2  [S0201]  48.93 16.24 270 bottom
PR6021  10K_1%_4  [R0402]  48.35 13.98 270 bottom
PR6022  *short_2  [S0201]  48.19 16.24 270 bottom
PR6023  *short_2  [S0201]  26.94 27.24 0 top
PR6024  *100K_1%_4  [R0402]  44.18 15.33 90 top
PR6025  *short_6  [S0603]  40.41 13.21 0 bottom
PR6026  *short_2  [S0201]  44.58 13.51 180 bottom
PR6027  *short_4  [S0402]  27.24 26.4 0 top
PR6028  *short_2  [S0201]  25.31 29.3 270 top
PR6029  1K_1%_4  [R0402]  45.55 15.12 270 bottom
PR6030  *1K_1%_4  [R0402]  46.95 15.45 0 bottom
PR6031  *10K_1%_4  [R0402]  47.37 13.98 270 bottom
PR6414  *short_2  [S0201]  168.84 23.86 270 bottom
PR6416  100K_1%_2  [R0201]  164.4 29.45 0 top
PR6417  *short_2  [S0201]  163.51 26.28 270 top
PR6418  22.6K_1%_4  [R0402]  161.1 27.93 0 top
PR7000  2.2_5%_6  [R0603]  133.41 49.52 0 top
PR7001  100_1%_4  [R0402]  140.27 59.98 270 top
PR7002  *110_1%_4  [R0402]  141.26 59.98 270 top
PR7003  45.3_1%_4  [R0402]  142.3 60.06 270 top
PR7004  30K_1%_2  [R0201]  137.09 60.06 270 bottom
PR7005  39.2K_1%_2  [R0201]  141.79 55.87 180 top
PR7006  46.4K_1%_2  [R0201]  145.35 49.26 0 bottom
PR7007  100K_NTC_4_1%  [R0402]  130.26 58.48 90 bottom
PR7008  3.9_1%_4  [R0402]  141.79 54.85 0 top
PR7009  12.7K_1%_2  [R0201]  137.73 44.94 90 bottom
PR7010  12.7K_1%_2  [R0201]  133.44 54.49 180 top
PR7011  *10K_1%_2  [R0201]  138.72 59.68 90 bottom
PR7012  *short_2  [S0201]  139.43 59.68 90 bottom
PR7013  22.6K_1%_4  [R0402]  145.35 50.28 0 bottom
PR7014  2.32K_1%_4  [R0402]  142.43 50.28 0 bottom
PR7015  49.9_1%_4  [R0402]  142.23 59.99 90 bottom
PR7016  1.05K_1%_4  [R0402]  137.73 46.72 270 bottom
PR7017  1.05K_1%_4  [R0402]  133.44 53.53 180 top
PR7018  5.6M_1%_4  [R0402]  135.7 55.87 0 top
PR7019  10_1%_2  [R0201]  140.28 59.99 270 bottom
PR7020  *short_4  [S0402]  141.25 59.99 270 bottom
PR7021  100K_NTC_4_1%  [R0402]  125.07 79.85 315 bottom
PR7022  5.9K_1%_2  [R0201]  143.83 50.28 0 top
PR7023  12.7K_1%_2  [R0201]  143.83 49.26 0 top
PR7024  37.4K_1%_2  [R0201]  140.32 49.44 0 top
PR7025  *short_4  [S0402]  141.92 61.71 180 bottom
PR7026  5.6M_1%_4  [R0402]  136.71 48.5 270 bottom
PR7027  49.9_1%_4  [R0402]  142.05 50.28 0 top
PR7028  69.8_1%_4  [R0402]  142.05 49.26 0 top
PR7029  649_1%_4  [R0402]  138.49 49.26 0 top
PR7030  14K_1%_2  [R0201]  136.71 46.72 270 bottom
PR7031  14K_1%_2  [R0201]  135.7 53.83 0 top
PR7032  100K_NTC_4_1%  [R0402]  126.91 73.04 270 bottom
PR7033  10.5K_1%_2  [R0201]  136.71 44.94 270 bottom
PR7034  10.5K_1%_2  [R0201]  135.7 52.82 0 top
PR7035  3.16K_1%_4  [R0402]  139.63 51.8 180 top
PR7036  7.32K_1%_2  [R0201]  139.63 50.79 180 top
PR7037  10.5K_1%_2  [R0201]  136.71 49.52 180 top
PR7038  7.5K_1%_2  [R0201]  137.22 50.53 0 top
PR7039  *short_2  [S0201]  141.16 51.93 0 top
PR7040  301_1%_2  [R0201]  139.38 53.2 90 top
PR7041  100_1%_4  [R0402]  137.73 51.55 180 top
PR7042  *10K_1%_4  [R0402]  141.67 52.95 180 top
PR7043  100_1%_4  [R0402]  118.8 54.23 180 top
PR7044  *short_4  [S0402]  118.8 53.22 180 top
PR7045  100_1%_4  [R0402]  118.59 49.23 180 top
PR7046  *short_4  [S0402]  118.59 50.2 180 top
PR7047  10K_1%_4  [R0402]  143.01 46.82 90 bottom
PR7048  SP@63.4K_1%_4  [R0402]  142.45 49.14 0 bottom
PR7049  *10K_1%_4  [R0402]  142.05 46.82 270 bottom
PR7050  100_1%_4  [R0402]  94.93 78.83 90 top
PR7051  *short_4  [S0402]  95.21 80.85 270 top
PR7052  100_1%_4  [R0402]  96.66 78.6 90 top
PR7053  *short_4  [S0402]  96.58 80.9 270 top
PR7054  10K_1%_4  [R0402]  133.4 57.08 0 bottom
PR7055  26.1K_1%_4  [R0402]  133.4 59.03 0 bottom
PR7056  *10K_1%_4  [R0402]  133.4 55.14 180 bottom
PR7057  100_1%_4  [R0402]  115.4 44.03 0 top
PR7058  *short_4  [S0402]  117.13 44.03 180 top
PR7059  10K_1%_4  [R0402]  145.82 52.69 90 bottom
PR7060  100K_1%_4  [R0402]  143.8 55.15 90 bottom
PR7061  100_1%_4  [R0402]  115.25 45.76 0 top
PR7062  *short_4  [S0402]  117 45.76 180 top
PR7063  *10K_1%_4  [R0402]  145.98 51.74 270 top
PR7064  10_5%_6  [R0603]  133.67 51.73 90 top
PR7065  SP@10K_1%_4  [R0402]  141.03 44.94 270 bottom
PR7066  SP@0_5%_4  [R0402]  141.03 48.5 270 bottom
PR7067  *short_2  [S0201]  143.44 57.52 270 bottom
PR7068  10K_1%_2  [R0201]  143.44 58.53 270 bottom
PR7069  SP@10K_1%_4  [R0402]  142.05 45.1 270 bottom
PR7072  *2.2_5%_6  [R0603]  131.35 63.54 90 bottom
PR7073  *short_2  [S0201]  127.93 62.47 180 bottom
PR7074  *short_2  [S0201]  124.24 62.47 0 bottom
PR7075  *365_1%_4  [R0402]  138.75 46.72 270 bottom
PR7076  536_1%_4  [R0402]  138.75 44.94 270 bottom
PR7077  *U42P@short_4  [S0402]  133.13 51.24 0 bottom
PR7078  U42P@1_5%_6  [R0603]  129.04 43.6 270 bottom
PR7079  *U42P@short_4  [S0402]  135.19 46.09 0 bottom
PR7080  U42P@2.2_1%_6  [R0603]  135.09 48.65 270 bottom
PR7081  *U42P@2.2_5%_6  [R0603]  131.38 53.91 270 bottom
PR7082  *short_2  [S0201]  127.66 56.37 180 bottom
PR7083  *short_2  [S0201]  124.24 55.15 0 bottom
PR7084  U42P@536_1%_4  [R0402]  141 46.72 90 bottom
PR7085  *U42P@365_1%_4  [R0402]  139.82 46.5 90 bottom
PR7087  *2.2_5%_6  [R0603]  136.64 40.39 90 top
PR7088  *short_2  [S0201]  131.41 38.86 180 bottom
PR7089  *short_2  [S0201]  128.01 38.86 0 bottom
PR7090  309_1%_4  [R0402]  143.32 58.66 180 top
PR7091  182_1%_2  [R0201]  143.5 55.08 90 top
PR7092  4.7K_1%_2  [R0201]  144.46 55.08 90 top
PR7093  4.7K_NTC_4_1%  [R0402]  132.81 42.73 0 bottom
PR7095  *2.2_5%_6  [R0603]  118.55 76.81 45 top
PR7096  *short_2  [S0201]  113.83 79.06 180 bottom
PR7097  *short_2  [S0201]  110.17 79.06 0 bottom
PR7098  649_1%_4  [R0402]  136.84 59.3 180 top
PR7099  715_1%_4  [R0402]  133.89 55.87 90 top
PR7100  4.75K_1%_2  [R0201]  132.9 55.87 90 top
PR7101  4.7K_NTC_4_1%  [R0402]  113.75 83.2 0 bottom
PR7102  *short_4  [S0402]  139.25 59.3 270 top
PR7103  *10K_1%_4  [R0402]  133.39 53.17 0 bottom
PR7104  10K_1%_4  [R0402]  133.36 52.21 180 bottom
PR7105  *short_4  [S0402]  118.96 68.19 180 top
PR7106  1_5%_6  [R0603]  123.99 72.76 45 bottom
PR7107  *short_4  [S0402]  116.57 70.27 180 bottom
PR7108  2.2_1%_6  [R0603]  115.56 68.46 90 bottom
PR7109  *short_4  [S0402]  126.32 78.53 90 bottom
PR7110  1_5%_6  [R0603]  126.02 74.55 45 bottom
PR7111  *short_4  [S0402]  130.11 76.24 0 bottom
PR7112  2.2_1%_6  [R0603]  130.9 78.12 270 bottom
PR7113  *short_4  [S0402]  138.45 43.6 0 bottom
PR7114  1_5%_6  [R0603]  139.4 38.53 0 top
PR7115  *short_4  [S0402]  143.14 39.81 0 bottom
PR7116  2.2_1%_6  [R0603]  142.65 42.89 90 bottom
PR9000  EV@1_5%_6  [R0603]  67.96 115.73 90 bottom
PR9001  EV@1_5%_6  [R0603]  76.16 109.05 270 bottom
PR9002  EV@499K_1%_4  [R0402]  70.04 110.88 180 top
PR9004  *EV@2.2_5%_6  [R0603]  77.38 118.22 180 top
PR9006  EV@1_5%_6  [R0603]  73.73 115.18 0 bottom
PR9008  *EV@short_2  [S0201]  74.48 107.3 180 top
PR9009  *10K_1%_2  [R0201]  73.85 106.41 90 top
PR9011  EV@14.7K_1%_4  [R0402]  75.93 115.92 0 bottom
PR9012  *N17@1K_1%_4  [R0402]  74.86 115.45 270 top
PR9013  EV@10K_1%_4  [R0402]  72.91 106.67 270 top
PR9014  EV@1_5%_6  [R0603]  77.56 106.11 180 top
PR9015  *EV@short_2  [S0201]  71.66 113.45 0 top
PR9016  *EV@short_4  [S0402]  69.99 115.63 270 top
PR9017  *EV@short_2  [S0201]  72.05 114.16 180 top
PR9018  *N17@12K_1%_4  [R0402]  68.64 115.63 270 top
PR9019  *EV@2.2_5%_6  [R0603]  83.58 108.46 270 top
PR9021  SP@20.5K_1%_4  [R0402]  71.74 110.96 180 bottom
PR9022  *N17@10K_1%_4  [R0402]  70.98 115.63 270 top
PR9023  SP@6.19K_1%_4  [R0402]  73.14 112.91 270 bottom
PR9024  SP@4.32K_1%_4  [R0402]  71.77 111.92 0 bottom
PR9025  *EV@0_5%_2  [R0201]  73.72 105.14 180 top
PR9026  EV@100_1%_2  [R0201]  90.34 104.95 0 bottom
PR9027  SP@16.5K_1%_4  [R0402]  70.27 113.12 270 bottom
PR9028  *EV@short_2  [S0201]  69.4 107.81 180 bottom
PR9029  *EV@short_2  [S0201]  69.43 112.64 90 bottom
PR9030  SP@309_1%_4  [R0402]  70.55 114.49 0 bottom
PR9031  EV@100_1%_2  [R0201]  90.34 104.22 0 bottom
PR9032  EV@14.7K_1%_4  [R0402]  74.66 108.62 90 bottom
PR9033  EV@10K_1%_2  [R0201]  71.82 108.98 180 bottom
PR9034  *EV@short_2  [S0201]  77.58 111.11 0 top
PR9067  *EV@short_6  [S0603]  23.18 99.55 90 top
PR9068  *EV@short_6  [S0603]  25.33 99.55 270 top
PR9070  N17@0_5%_2  [R0201]  24.7 88.38 270 top
PR9072  N17@0_5%_2  [R0201]  22.95 87.44 0 top
PR9073  EV@5.6_5%_8  [R0805]  70.17 101.08 180 bottom
PR9074  EV@100K_1%_4  [R0402]  73.72 104.63 90 bottom
PR9075  EV@10K_1%_4  [R0402]  75.37 102.73 90 bottom
PR9076  N17@10K_1%_2  [R0201]  86.42 88.71 270 bottom
PR9077  EV@1M_5%_4  [R0402]  72.71 104.63 270 bottom
PR9078  N17@0_5%_2  [R0201]  79.56 97.9 270 bottom
PR9079  N17@0_5%_2  [R0201]  78.67 93.46 270 bottom
PR9080  EV@47_1%_4  [R0402]  75.63 93.86 90 bottom
PR9081  EV@133_1%_4  [R0402]  73.47 97.52 180 bottom
PR9082  EV@124_1%_4  [R0402]  73.47 96.13 180 bottom
PR9086  EV@100K_1%_4  [R0402]  140.07 63.49 90 bottom
PR9087  EV@10_5%_6  [R0603]  141.6 70.67 0 bottom
PR9088  EV@100K_1%_2  [R0201]  142.58 69.2 90 bottom
PR9089  EV@2.2_5%_6  [R0603]  139.56 71.36 90 bottom
PR9090  *EV@short_2  [S0201]  141.87 69.1 90 bottom
PR9091  *EV@0_5%_2  [R0201]  140.88 67.55 90 top
PR9092  *EV@4.7_5%_6  [R0603]  137.09 65.26 270 top
PR9093  *EV@short_2  [S0201]  141.51 66.68 0 top
PR9094  EV@6.49K_1%_4  [R0402]  141.46 63.82 0 bottom
PR9095  EV@2.2K_5%_2  [R0201]  141.72 66.71 0 bottom
PR9096  *EV@0_5%_4  [R0402]  141.72 65.75 0 bottom
PR9097  EV@9.31K_1%_4  [R0402]  141.46 62.85 180 bottom
PR9098  *EV@short_4  [S0402]  139.86 65.9 270 top
PR9099  EV@22_5%_8  [R0805]  139.15 79.31 0 top
PR9100  EV@100K_1%_4  [R0402]  133.23 79.06 180 top
PR9101  EV@1M_5%_4  [R0402]  133.54 77.46 90 top
PR9102  EV@1M_5%_6  [R0603]  121.47 124.83 0 top
PR9103  EV@22_5%_8  [R0805]  124.27 120.64 270 top
PR9104  EV@1M_5%_6  [R0603]  119.19 122.74 0 top
PR9105  *EV@100K_1%_6  [R0603]  126.93 120 0 bottom
PR9227  22_5%_8  [R0805]  11.36 22.87 90 bottom
PR9244  *short_8  [S0805]  160.39 23.58 0 top
PR9245  *short_8  [S0805]  151.52 25.87 0 top
PR9248  *short_8  [S0805]  19.52 22.13 270 top
PR9249  *short_8  [S0805]  18.98 31.36 0 top
PR9255  100K_1%_2  [R0201]  44.74 28.26 180 top
PR9256  *short_2  [S0201]  43.98 28.97 180 top
PR9258  *short_2  [S0201]  123.71 49.21 270 top
PR9259  *short_2  [S0201]  111.01 33.13 90 top
PR9263  *short_2  [S0201]  140.7 77.71 0 top
PR9264  *2.2_5%_6  [R0603]  61.91 116.37 180 top
PR9265  100K_1%_4  [R0402]  62.44 125.18 180 bottom
PR9266  *short_2  [S0201]  50.46 123.05 90 bottom
PR9267  *short_8  [S0805]  70.8 119.72 315 top
PR9268  *0_5%_2  [R0201]  159.7 26.02 180 top
PR9269  *short_2  [S0201]  159.83 26.91 90 top
PR9270  *0_5%_2  [R0201]  176.59 17.72 0 top
PR9271  *short_2  [S0201]  175.58 17.72 180 top
PR9272  *0_5%_2  [R0201]  122.97 49.21 270 top
PR9273  *short_2  [S0201]  65.37 123.07 0 bottom
PR9274  *EV@100K_NTC_4_1%  [R0402]  80.13 116.48 180 bottom
PR9275  N16@0_5%_8  [R0805]  19.49 94.35 270 top
PR9277  N16@0_5%_2  [R0201]  22.97 88.28 180 top
PR9278  N16@0_5%_4  [R0402]  76.13 116.19 90 top
PR9281  N17@0_5%_8  [R0805]  19.42 91.05 90 top
PR9282  N16@1K_5%_2  [R0201]  77.91 103.93 270 bottom
PR9283  EV@10K_1%_2  [R0201]  74.74 106.41 180 top
PR25541  N16@0_5%_2  [R0201]  25.59 88.38 270 top
PR25542  N17@0_5%_4  [R0402]  72.5 116.83 0 top
PU1  BQ24780SRUYR  [QFN28-4X4-4-38P]  134.48 29.91 0 bottom
PU16  G5335QT2U  [QFN23-4X4-5-25P]  117.97 38.09 270 bottom
PU26  G5416QS1U  [QFN30-4X4-4-32P]  64.07 119.9 180 top
PU3002  TMP708AIDBVR  [SOT23-2_8-95-5P-LP2985-50DBVT]  80.53 25.13 0 bottom
PU3003  JW5222RSOTB_TRPBF  [SOT23-2_8-95-6P-1_1H]  162.29 23.3 0 bottom
PU3004  JW5213DFND_TRPBF  [DFN8-2X2-5-9P-MAX8902B]  41.41 29.7 90 top
PU6000  RT6256BGQUF  [QFN12-3X3-45-0_6H]  145.27 31.43 270 bottom
PU6001  JW7110DFNC_TRPBF  [DFN14-3X2-4-15P-0_85H]  154.85 26.73 180 top
PU6002  JW7110DFNC_TRPBF  [DFN14-3X2-4-15P-0_85H]  22.01 27.27 90 top
PU6003  RT6258CGQUF  [QFN12-3X3-45-0_6H]  44 18.83 90 bottom
PU7000  RT3602AJGQW  [QFN48-6X6-4-49P-EXC7900-SG11]  138.75 54.47 180 bottom
PU7001  U42P@RT9610CGQW  [DFN8-2X2-5-9P]  133.11 47.99 180 bottom
PU7002  RT9610CGQW  [DFN8-2X2-5-9P]  118.71 69.12 0 bottom
PU7003  RT9610CGQW  [DFN8-2X2-5-9P]  128 77.53 180 bottom
PU7004  RT9610CGQW  [DFN8-2X2-5-9P]  140.73 41.37 180 bottom
PU9000  EV@RT8813DGQW  [QFN24-4X4-5-25P-RT8813D]  73.98 110.78 180 top
PU9002  EV@JW7110DFNC_TRPBF  [DFN14-3X2-4-15P-0_85H]  22.54 93.59 0 top
PU9003  EV@G9336ADJTP1U  [TSOT23-6-2_8-95-6P-1H]  77.53 97.14 90 bottom
PU9004  EV@G5335QT2U  [QFN23-4X4-5-25P]  137.81 66.69 270 bottom
Q9  EV@PJA138K  [SOT23-2-95-3P]  97.19 124.22 270 bottom
Q13  EV@PJT138K  [SC70-2_1-65-6P]  107.38 86.22 270 top
Q14  EV@DMG1012T-7  [SOT23-1_38-5-3P]  93.7 118.42 180 bottom
Q15  *EV@DMG1012T-7  [SOT23-1_38-5-3P]  100.77 124.57 270 top
Q16  EV@DMG1012T-7  [SOT23-1_38-5-3P]  89.22 117.84 180 bottom
Q20  EV@DMG1012T-7  [SOT23-1_38-5-3P]  136.21 101.08 0 top
Q21  *PJA138K  [SOT23-2-95-3P]  207.43 22.59 90 top
Q27  2N7002KDW  [SOT363-2_1-65-6P]  92.92 26.7 180 top
Q29  *BSS138BK  [SOT23-2_38-95-3P]  67.55 17.26 90 top
Q30  KBL@DMP2130L-7  [SOT23-2_38-95-3P]  196.86 15.84 90 bottom
Q31  KBL@DDTC144EUA-7-F  [SOT23-1_7-65-3P]  196.8 21.53 180 bottom
Q32  PBA@DMP2130L-7  [SOT23-2_38-95-3P]  63.26 23.13 0 bottom
Q33  *2N7002KTB  [SOT23-1_38-5-3P]  169.06 17.16 90 top
Q34  SSD@2N7002K  [SOT23-2-95-3P]  12.74 5.37 180 top
Q41  HDMI_N@SSM6N43FU  [SC70-2_1-65-6P]  24.95 64.63 90 top
Q63  2N7002KTB  [SOT23-1_38-5-3P]  173.34 17.64 180 top
Q81  PJA138K  [SOT23-2-95-3P]  24.95 41.64 270 top
Q2013  *2N7002K  [SOT23-2-95-3P]  65.21 49.59 180 top
Q2014  2N7002K  [SOT23-2-95-3P]  63.38 45.81 180 top
Q2023  *DDTC144EUA-7-F  [SOT23-1_7-65-3P]  69.51 81.82 180 bottom
Q2024  DMG301NU-7  [SOT23-2-95-3P]  110.65 64.38 270 bottom
Q2025  METR3904-G  [SOT23-2-95-3P]  113.45 61.12 0 bottom
Q2026  2N7002KDW  [SOT363-2_1-65-6P]  101.56 30.43 0 bottom
Q6505  TPC@2N7002K  [SOT23-2-95-3P]  8.6 23.28 270 bottom
Q6507  HDMI_N@2N7002K  [SOT23-2-95-3P]  20.69 87.41 270 top
Q6508  AP2331SA-7  [SOT23-2-95-3P]  16.7 87.13 180 top
Q6509  2N7002K  [SOT23-2-95-3P]  174.81 23.61 0 top
Q6512  EV@2N7002KTB  [SOT23-1_38-5-3P]  108.14 81.77 90 top
Q6515  TPC@2N7002K  [SOT23-2-95-3P]  13.19 9.08 270 top
Q6516  TPC@EMB20P03V  [POWER-3X3-65-5P]  19.9 14.49 180 top
Q6518  TPC@MMBT3906-7-F  [SOT23-2-95-3P]  19.11 9.94 270 top
Q6519  TPC@2N7002KDW  [SOT363-2_1-65-6P]  23.02 11.97 180 top
Q6521  2N7002KDW  [SOT363-2_1-65-6P]  57.49 109.54 180 top
Q6522  DDTC144EUA-7-F  [SOT23-1_7-65-3P]  61.48 111.75 0 top
Q6523  METR3904-G  [SOT23-2-95-3P]  176.62 31.1 90 top
Q6531  2N7002K  [SOT23-2-95-3P]  56.68 102.88 90 top
Q6533  HDMI_N@DMN601K-7  [SOT23-2-95-3P]  25.82 72.5 180 top
Q6550  N16@MMBT3904T-7-F  [SOT23-1_38-5-3P]  90.23 102.6 270 bottom
Q6551  N16@LTC044EEBFS8TL  [SOT23-1_38-5-3P]  86.85 101.4 270 bottom
Q6554  N16@MMDT3904-7-F  [SOT363-2_1-65-6P-1_1H]  85.73 97.39 270 top
Q6555  N16@PJC138K  [SOT23-1_7-65-3P]  85.18 90.54 180 bottom
R36  *10K_4  [R0402]  75.55 21.65 90 top
R38  100K_1%_4  [R0402]  61.45 39.58 0 top
R134  10K_5%_2  [R0201]  96.79 25.66 0 bottom
R180  20K_1%_2  [R0201]  194.47 24.55 180 bottom
R183  *4.7K_5%_4  [R0402]  193.03 24.7 0 bottom
R226  *short_2  [S0201]  62.75 35.55 0 top
R296  *EV@short_4  [S0402]  102.63 124.8 270 top
R297  N17@10K_1%_4  [R0402]  95.82 122.03 180 bottom
R299  *EV@short_4  [S0402]  87.95 108.06 0 top
R306  EV@100K_1%_4  [R0402]  116.77 122.8 180 top
R307  *EV@200_1%_4  [R0402]  114.87 117.84 0 bottom
R311  EV@10K_1%_4  [R0402]  102.17 117.72 180 bottom
R312  EV@2.49K_1%_4  [R0402]  115.76 119.24 0 bottom
R313  EV@10K_1%_4  [R0402]  90.58 105.82 0 bottom
R314  EV@10K_1%_4  [R0402]  119.19 100.44 270 bottom
R315  EV@10K_1%_4  [R0402]  119.57 99.05 0 bottom
R316  EV@10K_1%_4  [R0402]  120.33 98.03 0 bottom
R317  EV@10K_1%_4  [R0402]  120.2 104.63 0 top
R318  EV@40.2_1%_4  [R0402]  120.2 93.08 0 top
R319  EV@40.2_1%_4  [R0402]  120.2 94.09 0 top
R320  EV@60.4_1%_4  [R0402]  120.2 94.09 180 bottom
R321  *EV@60.4_4  [R0402]  110.43 97.11 180 top
R322  *EV@60.4_4  [R0402]  110.76 100.01 90 top
R323  *EV@0_5%_4  [R0402]  98.84 119.52 180 bottom
R324  *EV@short_4  [S0402]  97.42 120.69 90 bottom
R325  EV@100K_1%_4  [R0402]  103.57 120 180 bottom
R326  N16@1.8K_5%_4  [R0402]  91.2 89.01 90 bottom
R329  N17@0_5%_4  [R0402]  97.47 102.48 90 top
R330  *EV@10K_1%_4  [R0402]  98.23 87.49 90 bottom
R331  EV@10K_1%_4  [R0402]  98.61 89.27 90 bottom
R332  EV@10K_1%_4  [R0402]  97.65 89.27 90 bottom
R340  10K_1%_2  [R0201]  199.96 12.08 270 top
R341  EV_SP@100K_5%_4  [R0402]  110.91 80.63 90 top
